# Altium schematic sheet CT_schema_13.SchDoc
size 741 x 377 mm
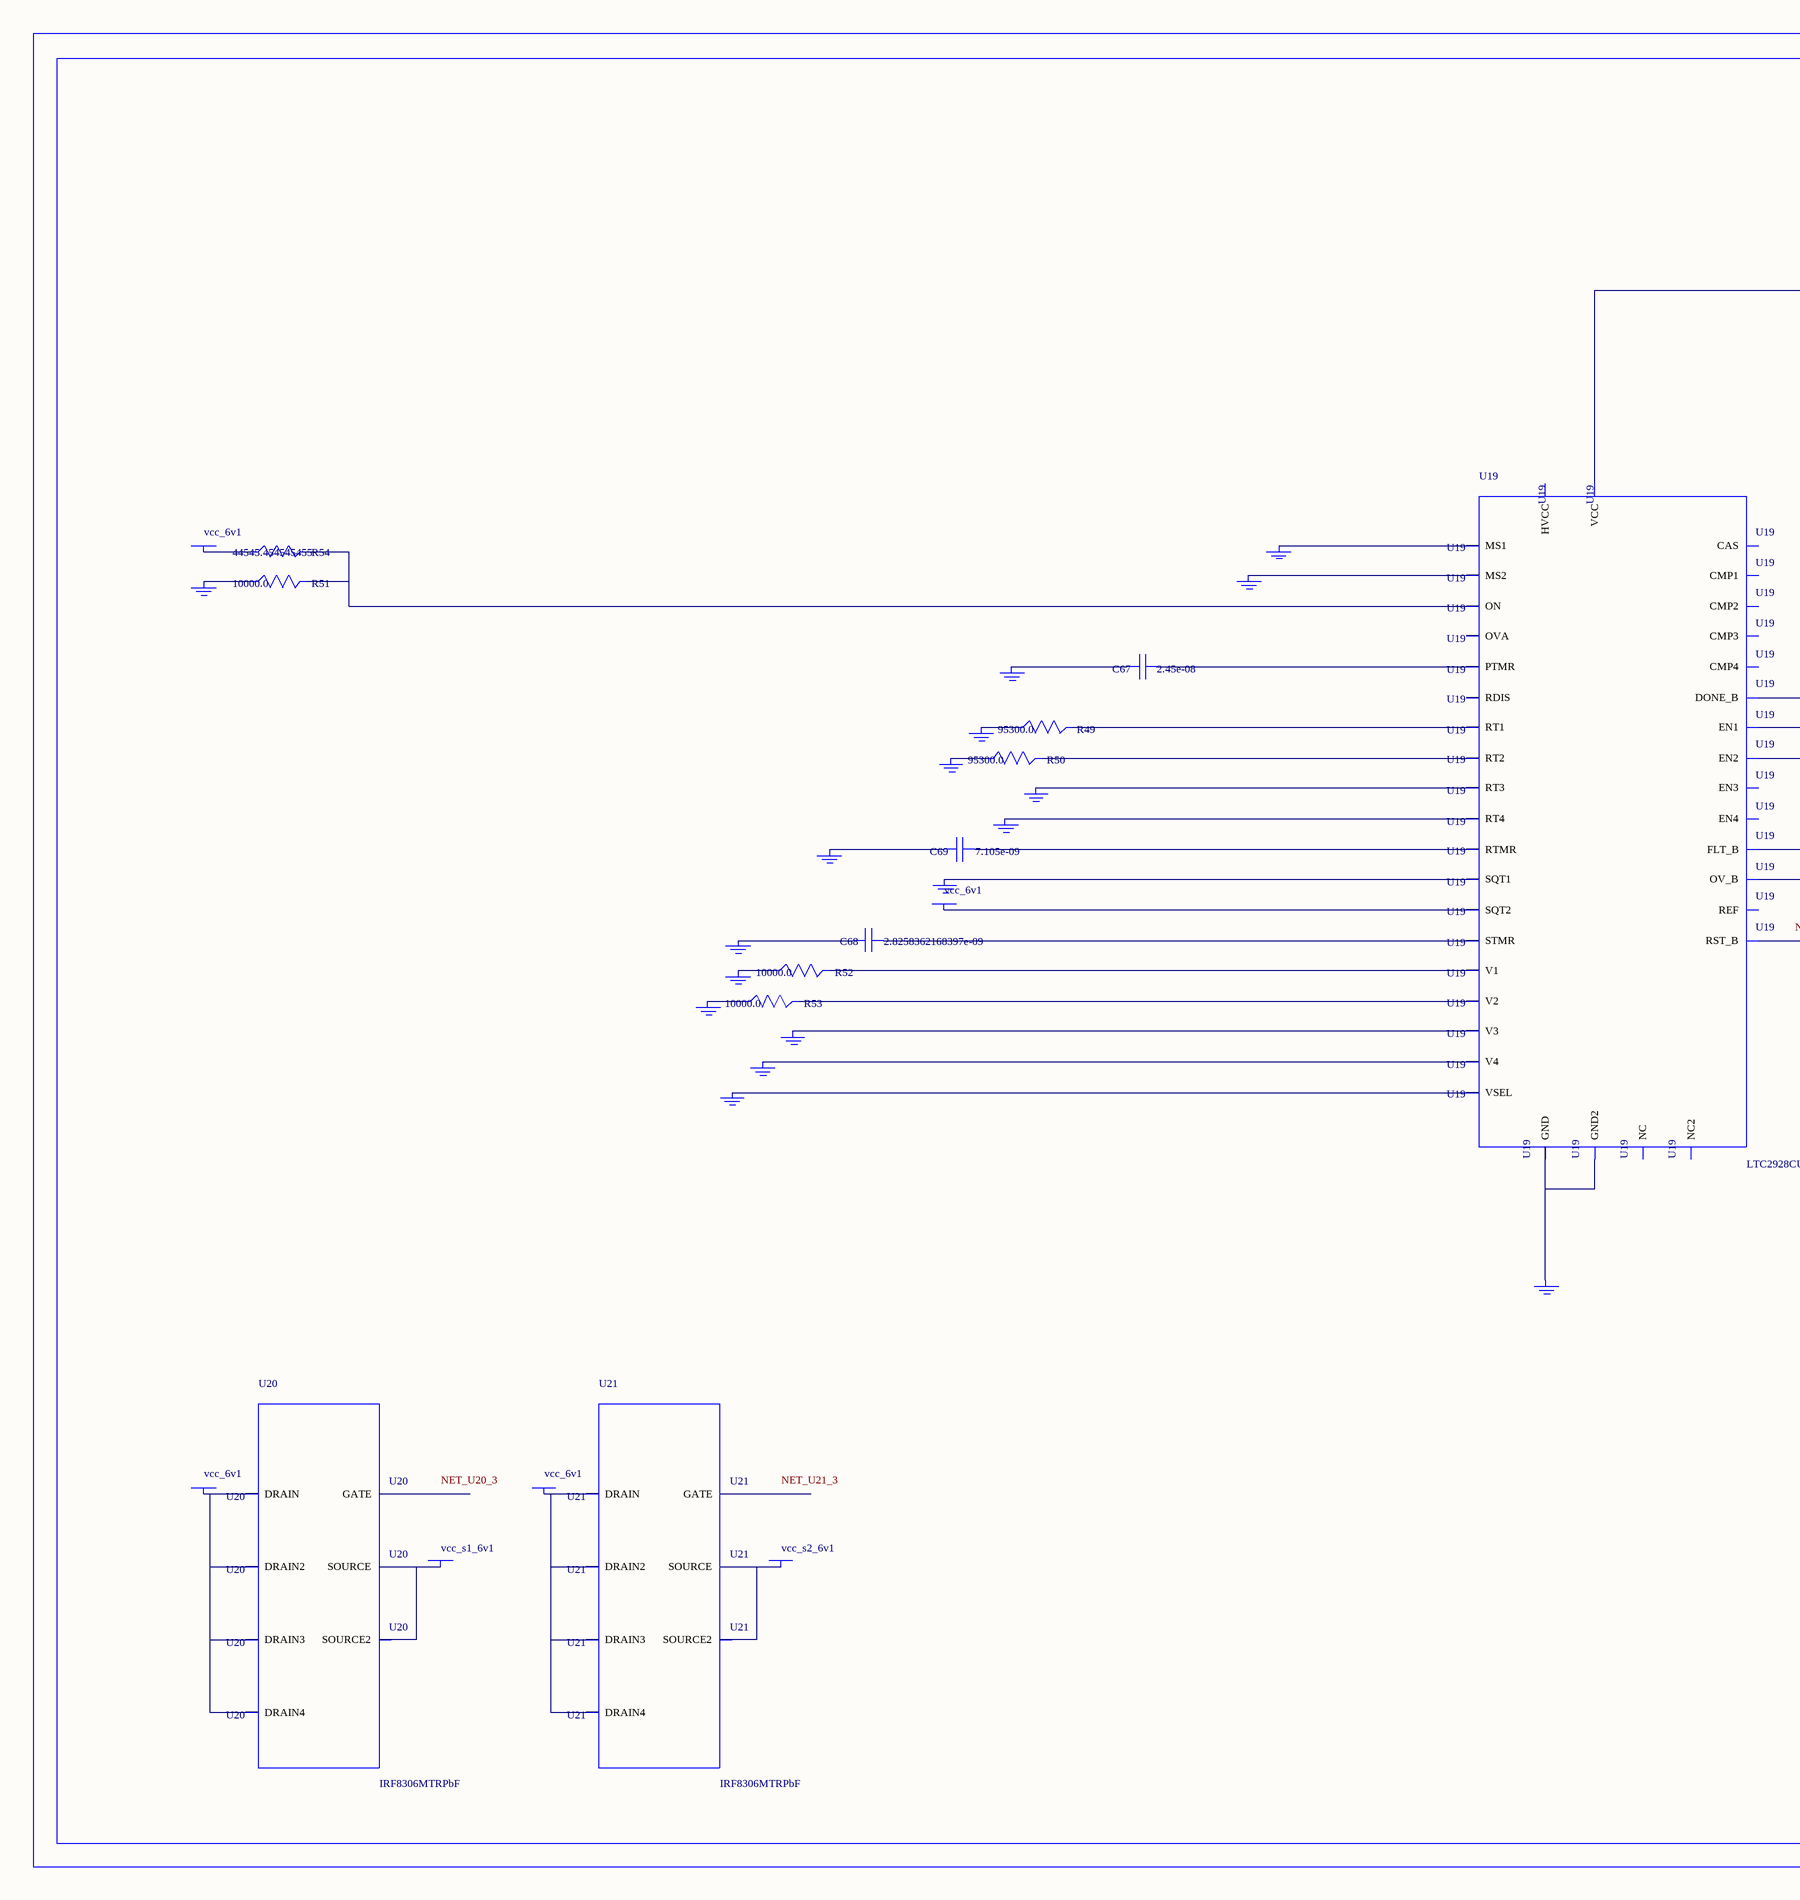
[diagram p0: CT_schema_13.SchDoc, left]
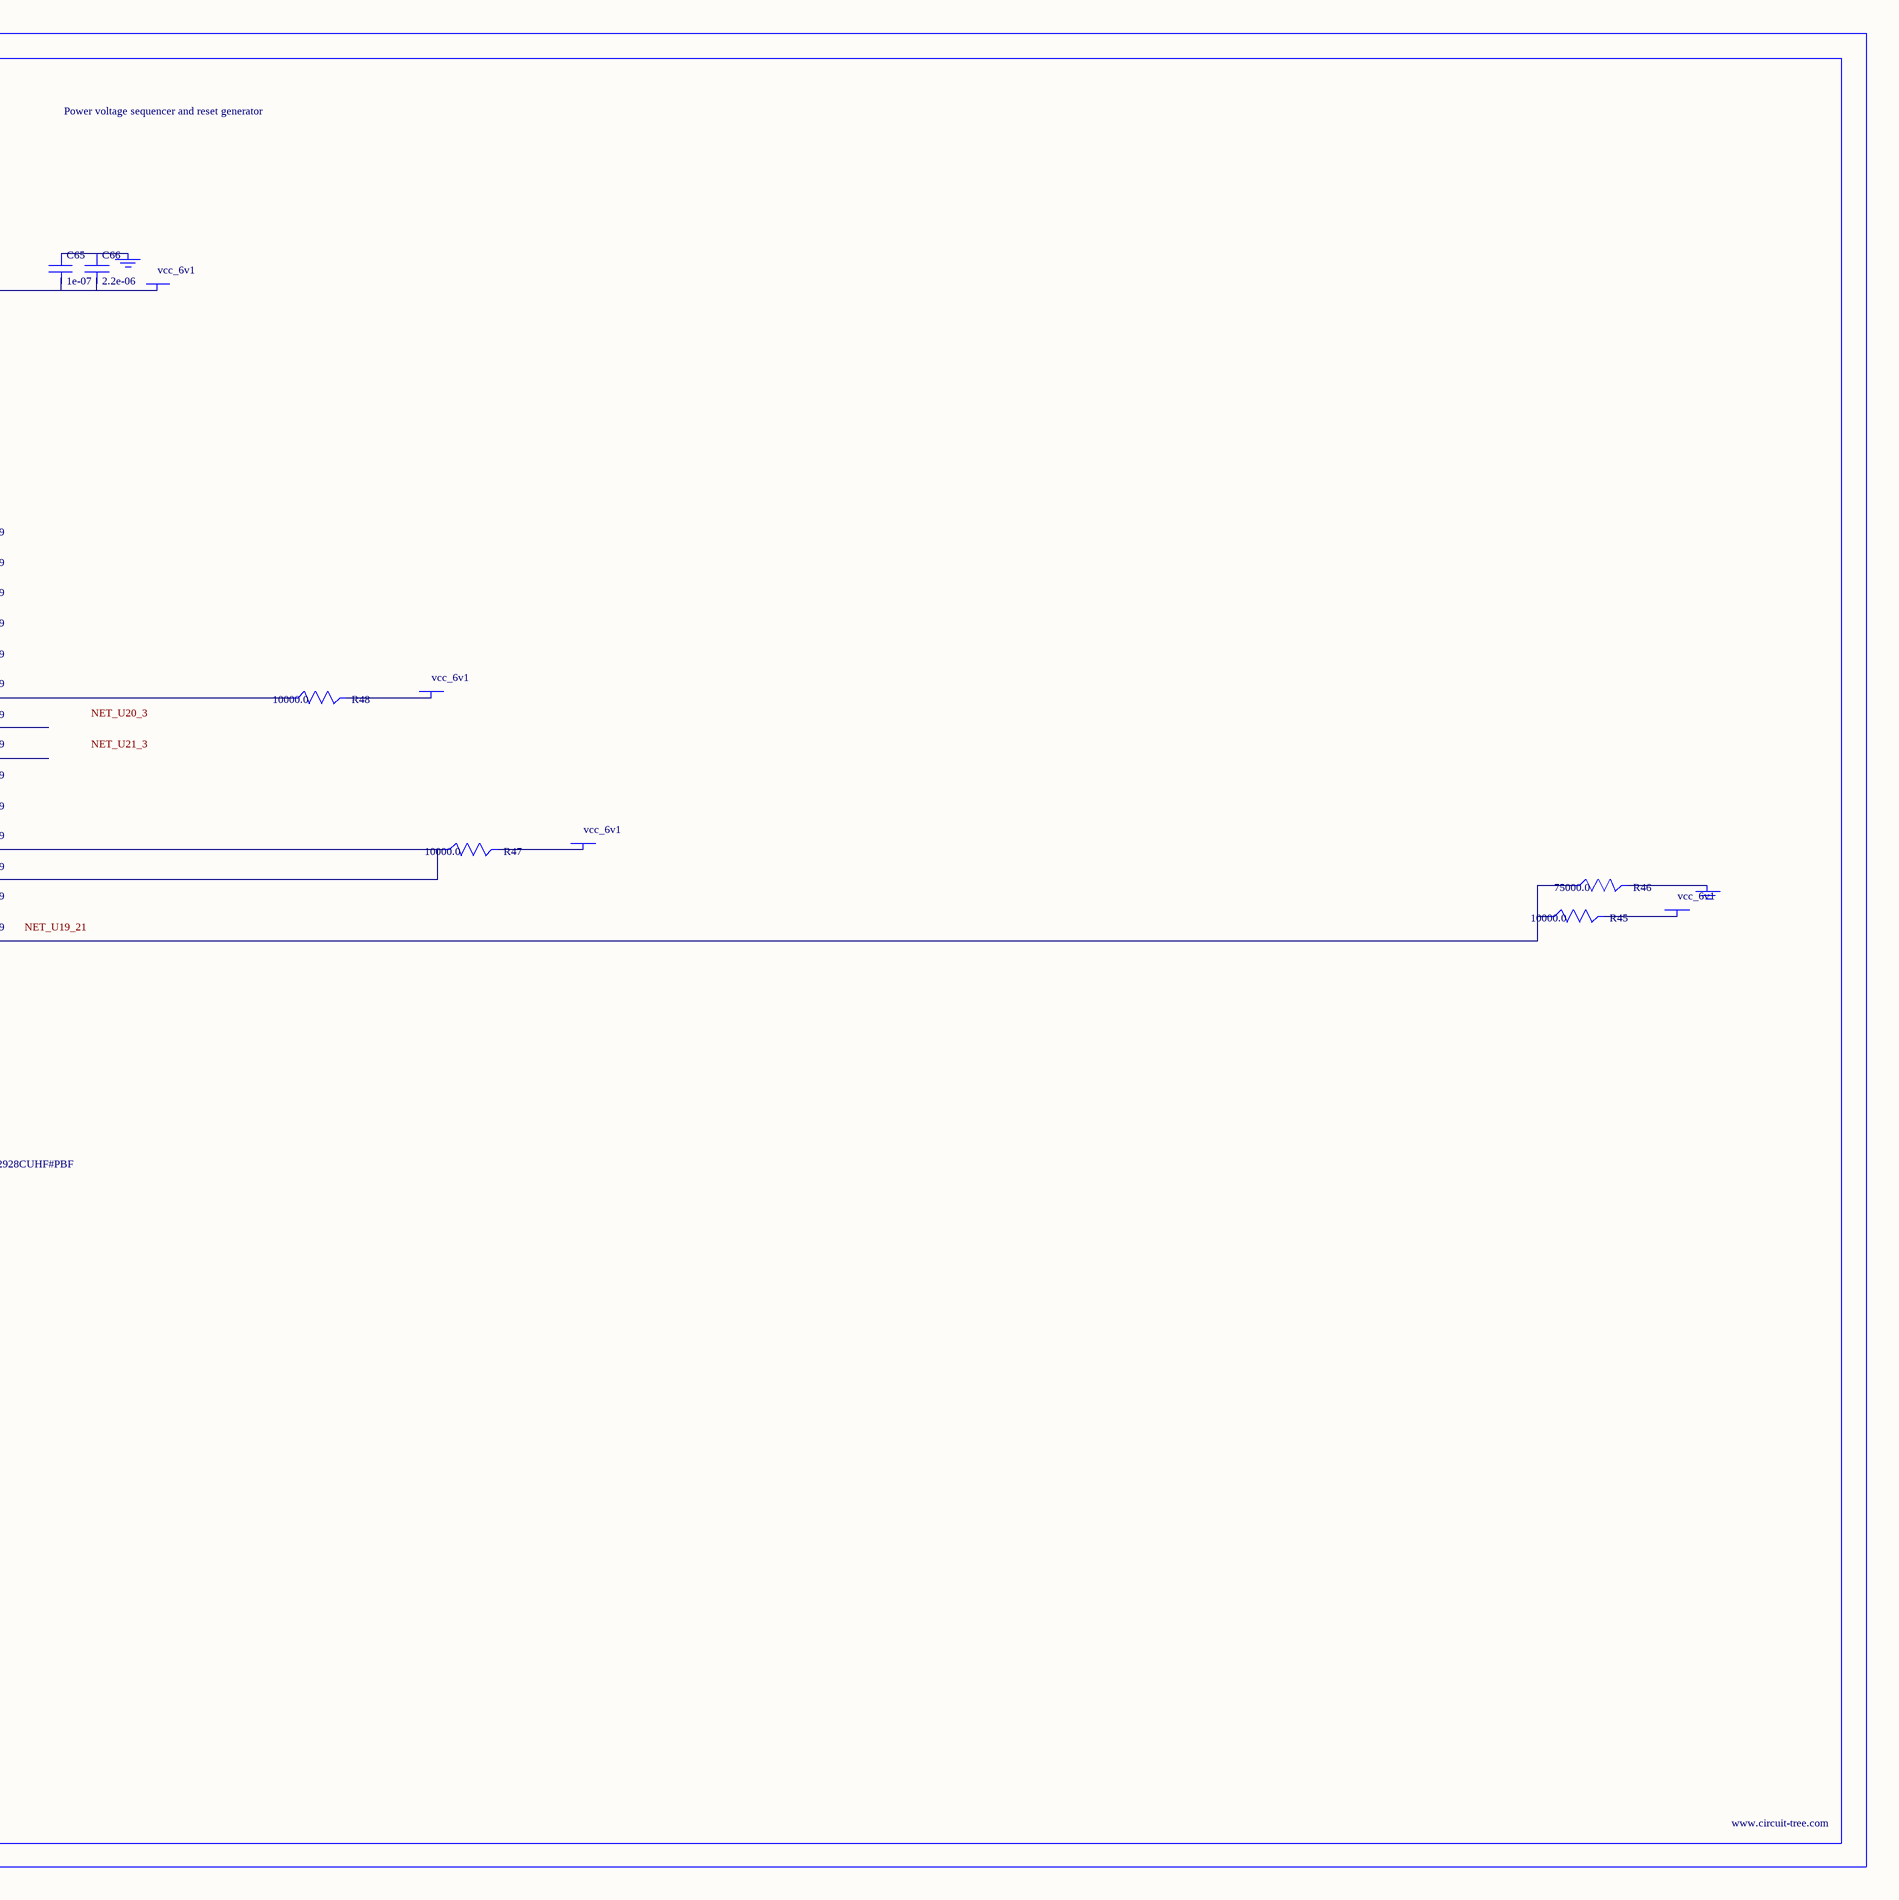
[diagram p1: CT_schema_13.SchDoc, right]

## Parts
BORDER12  (no value)
C65  1e-07  [C0402]
C66  2.2e-06  [C0603]
C67  2.45e-08  [R0603]
C68  2.8258362168397e-09  [R0603]
C69  7.105e-09  [R0603]
GND_INSTANCE_12_0  (no value)
GND_INSTANCE_12_1  (no value)
GND_INSTANCE_12_2  (no value)
GND_INSTANCE_12_3  (no value)
GND_INSTANCE_12_4  (no value)
GND_INSTANCE_12_5  (no value)
GND_INSTANCE_12_6  (no value)
GND_INSTANCE_12_7  (no value)
GND_INSTANCE_12_8  (no value)
GND_INSTANCE_12_9  (no value)
GND_INSTANCE_12_10  (no value)
GND_INSTANCE_12_11  (no value)
GND_INSTANCE_12_12  (no value)
GND_INSTANCE_12_13  (no value)
GND_INSTANCE_12_14  (no value)
GND_INSTANCE_12_15  (no value)
GND_INSTANCE_12_16  (no value)
GND_INSTANCE_12_17  (no value)
GND_INSTANCE_12_18  (no value)
POWER_INSTANCE_12_0  vcc_6v1
POWER_INSTANCE_12_1  vcc_6v1
POWER_INSTANCE_12_2  vcc_6v1
POWER_INSTANCE_12_3  vcc_6v1
POWER_INSTANCE_12_4  vcc_6v1
POWER_INSTANCE_12_5  vcc_6v1
POWER_INSTANCE_12_6  vcc_6v1
POWER_INSTANCE_12_7  vcc_s1_6v1
POWER_INSTANCE_12_8  vcc_6v1
POWER_INSTANCE_12_9  vcc_s2_6v1
R45  10000.0  [R0603]
R46  75000.0  [R0603]
R47  10000.0  [R0603]
R48  10000.0  [R0603]
R49  95300.0  [R0603]
R50  95300.0  [R0603]
R51  10000.0  [R0603]
R52  10000.0  [R0603]
R53  10000.0  [R0603]
R54  44545.454545455  [R0603]
U19  LTC2928CUHF#PBF  [QFN-38_UHF]
U20  IRF8306MTRPbF  [IRF8306MTRPBF]
U21  IRF8306MTRPbF  [IRF8306MTRPBF]

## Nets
NetC65_1: C65.1 C66.1 GND_INSTANCE_12_10.0(GND)
NetC65_2: C65.2 C66.2 POWER_INSTANCE_12_5.0(PWR) U19.22(VCC)
NetC67_1: C67.1 U19.27(PTMR)
NetC67_2: C67.2 GND_INSTANCE_12_13.0(GND)
NetC68_1: C68.1 U19.26(STMR)
NetC68_2: C68.2 GND_INSTANCE_12_12.0(GND)
NetC69_1: C69.1 U19.28(RTMR)
NetC69_2: C69.2 GND_INSTANCE_12_14.0(GND)
NetGND_INSTANCE_12_0_0: GND_INSTANCE_12_0.0(GND) R52.1
NetGND_INSTANCE_12_1_0: GND_INSTANCE_12_1.0(GND) R49.1
NetGND_INSTANCE_12_2_0: GND_INSTANCE_12_2.0(GND) R50.1
NetGND_INSTANCE_12_3_0: GND_INSTANCE_12_3.0(GND) U19.8(RT3)
NetGND_INSTANCE_12_4_0: GND_INSTANCE_12_4.0(GND) U19.9(RT4)
NetGND_INSTANCE_12_5_0: GND_INSTANCE_12_5.0(GND) U19.10(SQT1)
NetGND_INSTANCE_12_6_0: GND_INSTANCE_12_6.0(GND) U19.12(MS1)
NetGND_INSTANCE_12_7_0: GND_INSTANCE_12_7.0(GND) U19.13(MS2)
NetGND_INSTANCE_12_8_0: GND_INSTANCE_12_8.0(GND) R51.1
NetGND_INSTANCE_12_9_0: GND_INSTANCE_12_9.0(GND) R46.2
NetGND_INSTANCE_12_11_0: GND_INSTANCE_12_11.0(GND) U19.25(VSEL)
NetGND_INSTANCE_12_15_0: GND_INSTANCE_12_15.0(GND) U19.30(V4)
NetGND_INSTANCE_12_16_0: GND_INSTANCE_12_16.0(GND) U19.32(V3)
NetGND_INSTANCE_12_17_0: GND_INSTANCE_12_17.0(GND) R53.1
NetGND_INSTANCE_12_18_0: GND_INSTANCE_12_18.0(GND) U19.24(GND) U19.39(GND2)
NetPOWER_INSTANCE_12_0_0: POWER_INSTANCE_12_0.0(PWR) U19.11(SQT2)
NetPOWER_INSTANCE_12_1_0: POWER_INSTANCE_12_1.0(PWR) R54.1
NetPOWER_INSTANCE_12_2_0: POWER_INSTANCE_12_2.0(PWR) R48.2
NetPOWER_INSTANCE_12_3_0: POWER_INSTANCE_12_3.0(PWR) R47.2
NetPOWER_INSTANCE_12_4_0: POWER_INSTANCE_12_4.0(PWR) R45.2
NetPOWER_INSTANCE_12_6_0: POWER_INSTANCE_12_6.0(PWR) U20.1(DRAIN) U20.2(DRAIN2) U20.6(DRAIN3) U20.7(DRAIN4)
NetPOWER_INSTANCE_12_7_0: POWER_INSTANCE_12_7.0(PWR) U20.4(SOURCE) U20.5(SOURCE2)
NetPOWER_INSTANCE_12_8_0: POWER_INSTANCE_12_8.0(PWR) U21.1(DRAIN) U21.2(DRAIN2) U21.6(DRAIN3) U21.7(DRAIN4)
NetPOWER_INSTANCE_12_9_0: POWER_INSTANCE_12_9.0(PWR) U21.4(SOURCE) U21.5(SOURCE2)
NetR45_1: R45.1 R46.1 U19.21(RST_B)
NetR47_1: R47.1 U19.19(FLT_B) U19.20(OV_B)
NetR48_1: R48.1 U19.18(DONE_B)
NetR49_2: R49.2 U19.6(RT1)
NetR50_2: R50.2 U19.7(RT2)
NetR51_2: R51.2 R54.2 U19.16(ON)
NetR52_2: R52.2 U19.3(V1)
NetR53_2: R53.2 U19.38(V2)

Not connected (* = marked no-connect by the designer): U19 1(OVA) 2(EN1) 4(NC) 5(REF) 14(RDIS) 15(CAS) 17(NC2) 23(HVCC) 29(EN4) 31(EN3) 33(CMP3) 34(CMP4) 35(CMP1) 36(CMP2) 37(EN2); U20 3(GATE); U21 3(GATE)

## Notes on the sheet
- Labels drawn without touching a wire or pin: NET_U19_21, NET_U20_3, NET_U21_3

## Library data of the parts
BORDER12 = BORDER_PAGE12
C65 = C0402C104K3RACTU
C66 = GRM188R61H225KE1115D
C67 = C67
C68 = C68
C69 = C69
GND_INSTANCE_12_0-GND_INSTANCE_12_18 = GND
POWER_INSTANCE_12_0-POWER_INSTANCE_12_9 = PWR
R45 R47 R48 R51-R53 = RC0603JR-0710KL
R46 = RC0603JR-0775KL
R49 R50 = RC0603FR-0795K3L
R54 = R54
